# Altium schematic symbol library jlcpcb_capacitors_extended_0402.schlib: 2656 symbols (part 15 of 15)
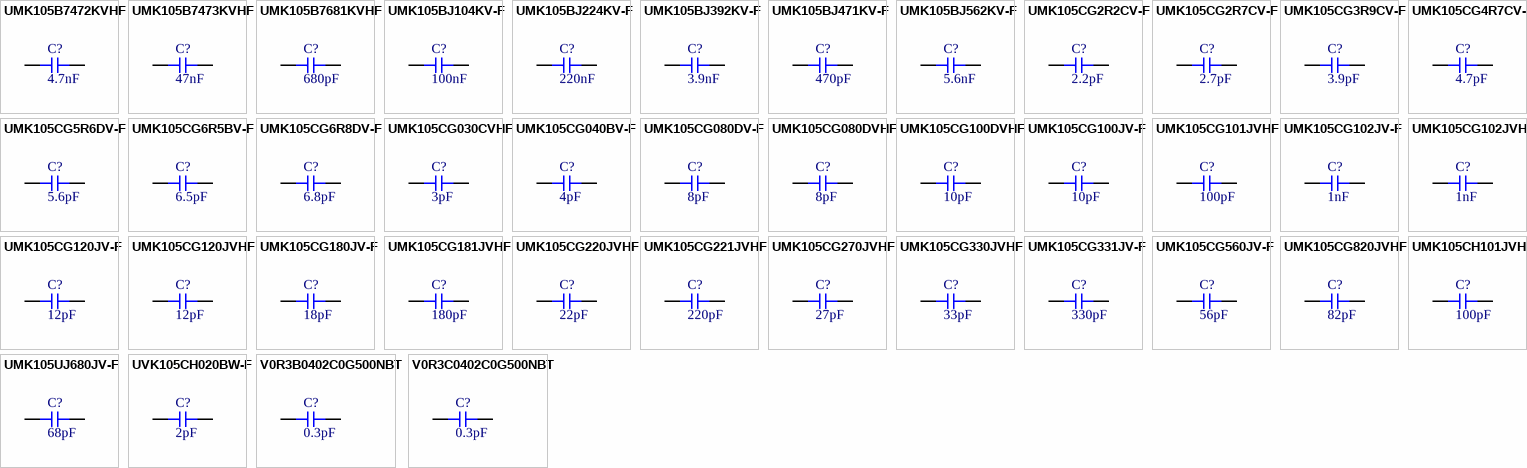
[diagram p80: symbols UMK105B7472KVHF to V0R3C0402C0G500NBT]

## UMK105CH101JVHF
designator C?  Capacitance: 100pF  (hidden comment: *)
Capacitor, Ceramic (MLCC), 100pF, ±5%, 50V, ±5%, SMD 0402; Manufacturer: Taiyo Yuden; Manufacturer Part Number: UMK105CH101JVHF
footprint CAP-0402 (0402 (1005M) Capacitor)
pins: 1, 2

## UMK105UJ680JV-F
designator C?  Capacitance: 68pF  (hidden comment: *)
Capacitor, Ceramic (MLCC), 68pF, ±5%, 50V, U2J, ±5%, SMD 0402; Manufacturer: Taiyo Yuden; Manufacturer Part Number: UMK105UJ680JV-F
footprint CAP-0402 (0402 (1005M) Capacitor)
pins: 1, 2

## UVK105CH020BW-F
designator C?  Capacitance: 2pF  (hidden comment: *)
Capacitor, Ceramic (MLCC), 2pF, ±0.1pF, 50V, ±0.1pF, SMD 0402; Manufacturer: Taiyo Yuden; Manufacturer Part Number: UVK105CH020BW-F
footprint CAP-0402 (0402 (1005M) Capacitor)
pins: 1, 2

## V0R3B0402C0G500NBT
designator C?  Capacitance: 0.3pF  (hidden comment: *)
Capacitor, Ceramic (MLCC), 0.3pF, ±0.1pF, 50V, C0G, ±0.1pF, SMD 0402; Manufacturer: VIIYONG; Manufacturer Part Number: V0R3B0402C0G500NBT
footprint CAP-0402 (0402 (1005M) Capacitor)
pins: 1, 2

## V0R3C0402C0G500NBT
designator C?  Capacitance: 0.3pF  (hidden comment: *)
Capacitor, Ceramic (MLCC), 0.3pF, ±0.25pF, 50V, C0G, ±0.25pF, SMD 0402; Manufacturer: VIIYONG; Manufacturer Part Number: V0R3C0402C0G500NBT
footprint CAP-0402 (0402 (1005M) Capacitor)
pins: 1, 2

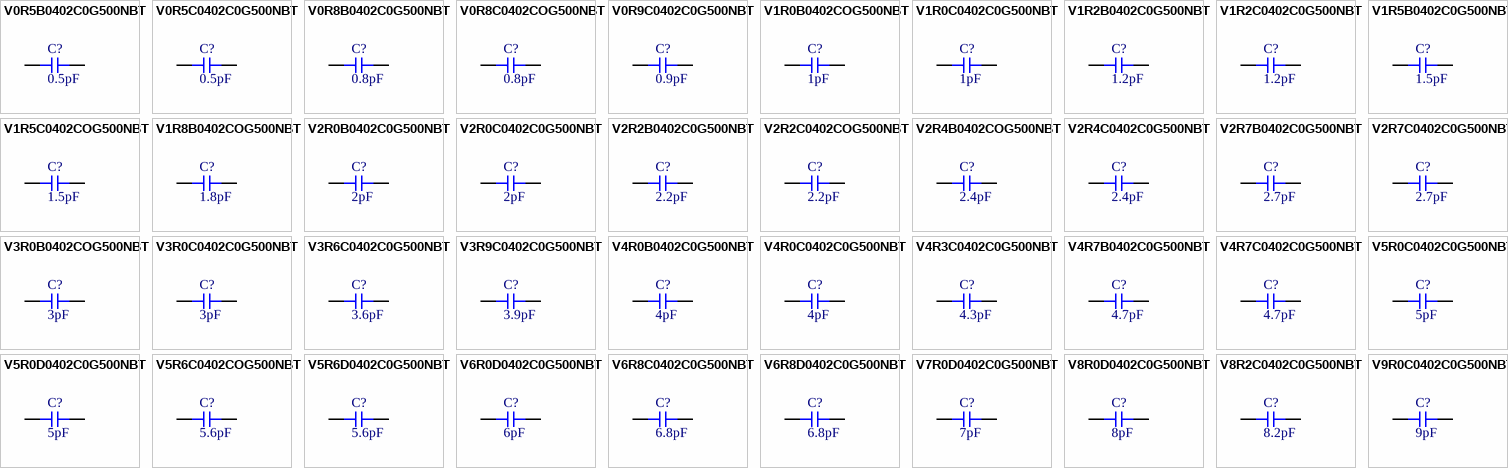
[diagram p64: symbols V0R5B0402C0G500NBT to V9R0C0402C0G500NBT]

## V0R5B0402C0G500NBT
designator C?  Capacitance: 0.5pF  (hidden comment: *)
Capacitor, Ceramic (MLCC), 0.5pF, ±0.1pF, 50V, C0G, ±0.1pF, SMD 0402; Manufacturer: VIIYONG; Manufacturer Part Number: V0R5B0402C0G500NBT
footprint CAP-0402 (0402 (1005M) Capacitor)
pins: 1, 2

## V0R5C0402C0G500NBT
designator C?  Capacitance: 0.5pF  (hidden comment: *)
Capacitor, Ceramic (MLCC), 0.5pF, ±0.25pF, 50V, C0G, ±0.25pF, SMD 0402; Manufacturer: VIIYONG; Manufacturer Part Number: V0R5C0402C0G500NBT
footprint CAP-0402 (0402 (1005M) Capacitor)
pins: 1, 2

## V0R8B0402C0G500NBT
designator C?  Capacitance: 0.8pF  (hidden comment: *)
Capacitor, Ceramic (MLCC), 0.8pF, ±0.1pF, 50V, C0G, ±0.1pF, SMD 0402; Manufacturer: VIIYONG; Manufacturer Part Number: V0R8B0402C0G500NBT
footprint CAP-0402 (0402 (1005M) Capacitor)
pins: 1, 2

## V0R8C0402COG500NBT
designator C?  Capacitance: 0.8pF  (hidden comment: *)
Capacitor, Ceramic (MLCC), 0.8pF, ±0.25pF, 50V, C0G, ±0.25pF, SMD 0402; Manufacturer: VIIYONG; Manufacturer Part Number: V0R8C0402COG500NBT
footprint CAP-0402 (0402 (1005M) Capacitor)
pins: 1, 2

## V0R9C0402C0G500NBT
designator C?  Capacitance: 0.9pF  (hidden comment: *)
Capacitor, Ceramic (MLCC), 0.9pF, ±0.25pF, 50V, C0G, ±0.25pF, SMD 0402; Manufacturer: VIIYONG; Manufacturer Part Number: V0R9C0402C0G500NBT
footprint CAP-0402 (0402 (1005M) Capacitor)
pins: 1, 2

## V1R0B0402COG500NBT
designator C?  Capacitance: 1pF  (hidden comment: *)
Capacitor, Ceramic (MLCC), 1pF, ±0.1pF, 50V, C0G, ±0.1pF, SMD 0402; Manufacturer: VIIYONG; Manufacturer Part Number: V1R0B0402COG500NBT
footprint CAP-0402 (0402 (1005M) Capacitor)
pins: 1, 2

## V1R0C0402C0G500NBT
designator C?  Capacitance: 1pF  (hidden comment: *)
Capacitor, Ceramic (MLCC), 1pF, ±0.25pF, 50V, C0G, ±0.25pF, SMD 0402; Manufacturer: VIIYONG; Manufacturer Part Number: V1R0C0402C0G500NBT
footprint CAP-0402 (0402 (1005M) Capacitor)
pins: 1, 2

## V1R2B0402C0G500NBT
designator C?  Capacitance: 1.2pF  (hidden comment: *)
Capacitor, Ceramic (MLCC), 1.2pF, ±0.1pF, 50V, C0G, ±0.1pF, SMD 0402; Manufacturer: VIIYONG; Manufacturer Part Number: V1R2B0402C0G500NBT
footprint CAP-0402 (0402 (1005M) Capacitor)
pins: 1, 2

## V1R2C0402C0G500NBT
designator C?  Capacitance: 1.2pF  (hidden comment: *)
Capacitor, Ceramic (MLCC), 1.2pF, ±0.25pF, 50V, C0G, ±0.25pF, SMD 0402; Manufacturer: VIIYONG; Manufacturer Part Number: V1R2C0402C0G500NBT
footprint CAP-0402 (0402 (1005M) Capacitor)
pins: 1, 2

## V1R5B0402C0G500NBT
designator C?  Capacitance: 1.5pF  (hidden comment: *)
Capacitor, Ceramic (MLCC), 1.5pF, ±0.1pF, 50V, C0G, ±0.1pF, SMD 0402; Manufacturer: VIIYONG; Manufacturer Part Number: V1R5B0402C0G500NBT
footprint CAP-0402 (0402 (1005M) Capacitor)
pins: 1, 2

## V1R5C0402COG500NBT
designator C?  Capacitance: 1.5pF  (hidden comment: *)
Capacitor, Ceramic (MLCC), 1.5pF, ±0.25pF, 50V, C0G, ±0.25pF, SMD 0402; Manufacturer: VIIYONG; Manufacturer Part Number: V1R5C0402COG500NBT
footprint CAP-0402 (0402 (1005M) Capacitor)
pins: 1, 2

## V1R8B0402COG500NBT
designator C?  Capacitance: 1.8pF  (hidden comment: *)
Capacitor, Ceramic (MLCC), 1.8pF, ±0.1pF, 50V, C0G, ±0.1pF, SMD 0402; Manufacturer: VIIYONG; Manufacturer Part Number: V1R8B0402COG500NBT
footprint CAP-0402 (0402 (1005M) Capacitor)
pins: 1, 2

## V2R0B0402C0G500NBT
designator C?  Capacitance: 2pF  (hidden comment: *)
Capacitor, Ceramic (MLCC), 2pF, ±0.1pF, 50V, C0G, ±0.1pF, SMD 0402; Manufacturer: VIIYONG; Manufacturer Part Number: V2R0B0402C0G500NBT
footprint CAP-0402 (0402 (1005M) Capacitor)
pins: 1, 2

## V2R0C0402C0G500NBT
designator C?  Capacitance: 2pF  (hidden comment: *)
Capacitor, Ceramic (MLCC), 2pF, ±0.25pF, 50V, C0G, ±0.25pF, SMD 0402; Manufacturer: VIIYONG; Manufacturer Part Number: V2R0C0402C0G500NBT
footprint CAP-0402 (0402 (1005M) Capacitor)
pins: 1, 2

## V2R2B0402C0G500NBT
designator C?  Capacitance: 2.2pF  (hidden comment: *)
Capacitor, Ceramic (MLCC), 2.2pF, ±0.1pF, 50V, C0G, ±0.1pF, SMD 0402; Manufacturer: VIIYONG; Manufacturer Part Number: V2R2B0402C0G500NBT
footprint CAP-0402 (0402 (1005M) Capacitor)
pins: 1, 2

## V2R2C0402COG500NBT
designator C?  Capacitance: 2.2pF  (hidden comment: *)
Capacitor, Ceramic (MLCC), 2.2pF, ±0.25pF, 50V, C0G, ±0.25pF, SMD 0402; Manufacturer: VIIYONG; Manufacturer Part Number: V2R2C0402COG500NBT
footprint CAP-0402 (0402 (1005M) Capacitor)
pins: 1, 2

## V2R4B0402COG500NBT
designator C?  Capacitance: 2.4pF  (hidden comment: *)
Capacitor, Ceramic (MLCC), 2.4pF, ±0.1pF, 50V, C0G, ±0.1pF, SMD 0402; Manufacturer: VIIYONG; Manufacturer Part Number: V2R4B0402COG500NBT
footprint CAP-0402 (0402 (1005M) Capacitor)
pins: 1, 2

## V2R4C0402C0G500NBT
designator C?  Capacitance: 2.4pF  (hidden comment: *)
Capacitor, Ceramic (MLCC), 2.4pF, ±0.25pF, 50V, C0G, ±0.25pF, SMD 0402; Manufacturer: VIIYONG; Manufacturer Part Number: V2R4C0402C0G500NBT
footprint CAP-0402 (0402 (1005M) Capacitor)
pins: 1, 2

## V2R7B0402C0G500NBT
designator C?  Capacitance: 2.7pF  (hidden comment: *)
Capacitor, Ceramic (MLCC), 2.7pF, ±0.1pF, 50V, C0G, ±0.1pF, SMD 0402; Manufacturer: VIIYONG; Manufacturer Part Number: V2R7B0402C0G500NBT
footprint CAP-0402 (0402 (1005M) Capacitor)
pins: 1, 2

## V2R7C0402C0G500NBT
designator C?  Capacitance: 2.7pF  (hidden comment: *)
Capacitor, Ceramic (MLCC), 2.7pF, ±0.25pF, 50V, C0G, ±0.25pF, SMD 0402; Manufacturer: VIIYONG; Manufacturer Part Number: V2R7C0402C0G500NBT
footprint CAP-0402 (0402 (1005M) Capacitor)
pins: 1, 2

## V3R0B0402COG500NBT
designator C?  Capacitance: 3pF  (hidden comment: *)
Capacitor, Ceramic (MLCC), 3pF, ±0.1pF, 50V, C0G, ±0.1pF, SMD 0402; Manufacturer: VIIYONG; Manufacturer Part Number: V3R0B0402COG500NBT
footprint CAP-0402 (0402 (1005M) Capacitor)
pins: 1, 2

## V3R0C0402C0G500NBT
designator C?  Capacitance: 3pF  (hidden comment: *)
Capacitor, Ceramic (MLCC), 3pF, ±0.25pF, 50V, C0G, ±0.25pF, SMD 0402; Manufacturer: VIIYONG; Manufacturer Part Number: V3R0C0402C0G500NBT
footprint CAP-0402 (0402 (1005M) Capacitor)
pins: 1, 2

## V3R6C0402C0G500NBT
designator C?  Capacitance: 3.6pF  (hidden comment: *)
Capacitor, Ceramic (MLCC), 3.6pF, ±0.25pF, 50V, C0G, ±0.25pF, SMD 0402; Manufacturer: VIIYONG; Manufacturer Part Number: V3R6C0402C0G500NBT
footprint CAP-0402 (0402 (1005M) Capacitor)
pins: 1, 2

## V3R9C0402C0G500NBT
designator C?  Capacitance: 3.9pF  (hidden comment: *)
Capacitor, Ceramic (MLCC), 3.9pF, ±0.25pF, 50V, C0G, ±0.25pF, SMD 0402; Manufacturer: VIIYONG; Manufacturer Part Number: V3R9C0402C0G500NBT
footprint CAP-0402 (0402 (1005M) Capacitor)
pins: 1, 2

## V4R0B0402C0G500NBT
designator C?  Capacitance: 4pF  (hidden comment: *)
Capacitor, Ceramic (MLCC), 4pF, ±0.1pF, 50V, C0G, ±0.1pF, SMD 0402; Manufacturer: VIIYONG; Manufacturer Part Number: V4R0B0402C0G500NBT
footprint CAP-0402 (0402 (1005M) Capacitor)
pins: 1, 2

## V4R0C0402C0G500NBT
designator C?  Capacitance: 4pF  (hidden comment: *)
Capacitor, Ceramic (MLCC), 4pF, ±0.25pF, 50V, C0G, ±0.25pF, SMD 0402; Manufacturer: VIIYONG; Manufacturer Part Number: V4R0C0402C0G500NBT
footprint CAP-0402 (0402 (1005M) Capacitor)
pins: 1, 2

## V4R3C0402C0G500NBT
designator C?  Capacitance: 4.3pF  (hidden comment: *)
Capacitor, Ceramic (MLCC), 4.3pF, ±0.25pF, 50V, C0G, ±0.25pF, SMD 0402; Manufacturer: VIIYONG; Manufacturer Part Number: V4R3C0402C0G500NBT
footprint CAP-0402 (0402 (1005M) Capacitor)
pins: 1, 2

## V4R7B0402C0G500NBT
designator C?  Capacitance: 4.7pF  (hidden comment: *)
Capacitor, Ceramic (MLCC), 4.7pF, ±0.1pF, 50V, C0G, ±0.1pF, SMD 0402; Manufacturer: VIIYONG; Manufacturer Part Number: V4R7B0402C0G500NBT
footprint CAP-0402 (0402 (1005M) Capacitor)
pins: 1, 2

## V4R7C0402C0G500NBT
designator C?  Capacitance: 4.7pF  (hidden comment: *)
Capacitor, Ceramic (MLCC), 4.7pF, ±0.25pF, 50V, C0G, ±0.25pF, SMD 0402; Manufacturer: VIIYONG; Manufacturer Part Number: V4R7C0402C0G500NBT
footprint CAP-0402 (0402 (1005M) Capacitor)
pins: 1, 2

## V5R0C0402C0G500NBT
designator C?  Capacitance: 5pF  (hidden comment: *)
Capacitor, Ceramic (MLCC), 5pF, ±0.25pF, 50V, C0G, ±0.25pF, SMD 0402; Manufacturer: VIIYONG; Manufacturer Part Number: V5R0C0402C0G500NBT
footprint CAP-0402 (0402 (1005M) Capacitor)
pins: 1, 2

## V5R0D0402C0G500NBT
designator C?  Capacitance: 5pF  (hidden comment: *)
Capacitor, Ceramic (MLCC), 5pF, ±0.5pF, 50V, C0G, ±0.5pF, SMD 0402; Manufacturer: VIIYONG; Manufacturer Part Number: V5R0D0402C0G500NBT
footprint CAP-0402 (0402 (1005M) Capacitor)
pins: 1, 2

## V5R6C0402COG500NBT
designator C?  Capacitance: 5.6pF  (hidden comment: *)
Capacitor, Ceramic (MLCC), 5.6pF, ±0.25pF, 50V, C0G, ±0.25pF, SMD 0402; Manufacturer: VIIYONG; Manufacturer Part Number: V5R6C0402COG500NBT
footprint CAP-0402 (0402 (1005M) Capacitor)
pins: 1, 2

## V5R6D0402C0G500NBT
designator C?  Capacitance: 5.6pF  (hidden comment: *)
Capacitor, Ceramic (MLCC), 5.6pF, ±0.5pF, 50V, C0G, ±0.5pF, SMD 0402; Manufacturer: VIIYONG; Manufacturer Part Number: V5R6D0402C0G500NBT
footprint CAP-0402 (0402 (1005M) Capacitor)
pins: 1, 2

## V6R0D0402C0G500NBT
designator C?  Capacitance: 6pF  (hidden comment: *)
Capacitor, Ceramic (MLCC), 6pF, ±0.5pF, 50V, C0G, ±0.5pF, SMD 0402; Manufacturer: VIIYONG; Manufacturer Part Number: V6R0D0402C0G500NBT
footprint CAP-0402 (0402 (1005M) Capacitor)
pins: 1, 2

## V6R8C0402C0G500NBT
designator C?  Capacitance: 6.8pF  (hidden comment: *)
Capacitor, Ceramic (MLCC), 6.8pF, ±0.25pF, 50V, C0G, ±0.25pF, SMD 0402; Manufacturer: VIIYONG; Manufacturer Part Number: V6R8C0402C0G500NBT
footprint CAP-0402 (0402 (1005M) Capacitor)
pins: 1, 2

## V6R8D0402C0G500NBT
designator C?  Capacitance: 6.8pF  (hidden comment: *)
Capacitor, Ceramic (MLCC), 6.8pF, ±0.5pF, 50V, C0G, ±0.5pF, SMD 0402; Manufacturer: VIIYONG; Manufacturer Part Number: V6R8D0402C0G500NBT
footprint CAP-0402 (0402 (1005M) Capacitor)
pins: 1, 2

## V7R0D0402C0G500NBT
designator C?  Capacitance: 7pF  (hidden comment: *)
Capacitor, Ceramic (MLCC), 7pF, ±0.5pF, 50V, C0G, ±0.5pF, SMD 0402; Manufacturer: VIIYONG; Manufacturer Part Number: V7R0D0402C0G500NBT
footprint CAP-0402 (0402 (1005M) Capacitor)
pins: 1, 2

## V8R0D0402C0G500NBT
designator C?  Capacitance: 8pF  (hidden comment: *)
Capacitor, Ceramic (MLCC), 8pF, ±0.5pF, 50V, C0G, ±0.5pF, SMD 0402; Manufacturer: VIIYONG; Manufacturer Part Number: V8R0D0402C0G500NBT
footprint CAP-0402 (0402 (1005M) Capacitor)
pins: 1, 2

## V8R2C0402C0G500NBT
designator C?  Capacitance: 8.2pF  (hidden comment: *)
Capacitor, Ceramic (MLCC), 8.2pF, ±0.25pF, 50V, C0G, ±0.25pF, SMD 0402; Manufacturer: VIIYONG; Manufacturer Part Number: V8R2C0402C0G500NBT
footprint CAP-0402 (0402 (1005M) Capacitor)
pins: 1, 2

## V9R0C0402C0G500NBT
designator C?  Capacitance: 9pF  (hidden comment: *)
Capacitor, Ceramic (MLCC), 9pF, ±0.25pF, 50V, C0G, ±0.25pF, SMD 0402; Manufacturer: VIIYONG; Manufacturer Part Number: V9R0C0402C0G500NBT
footprint CAP-0402 (0402 (1005M) Capacitor)
pins: 1, 2

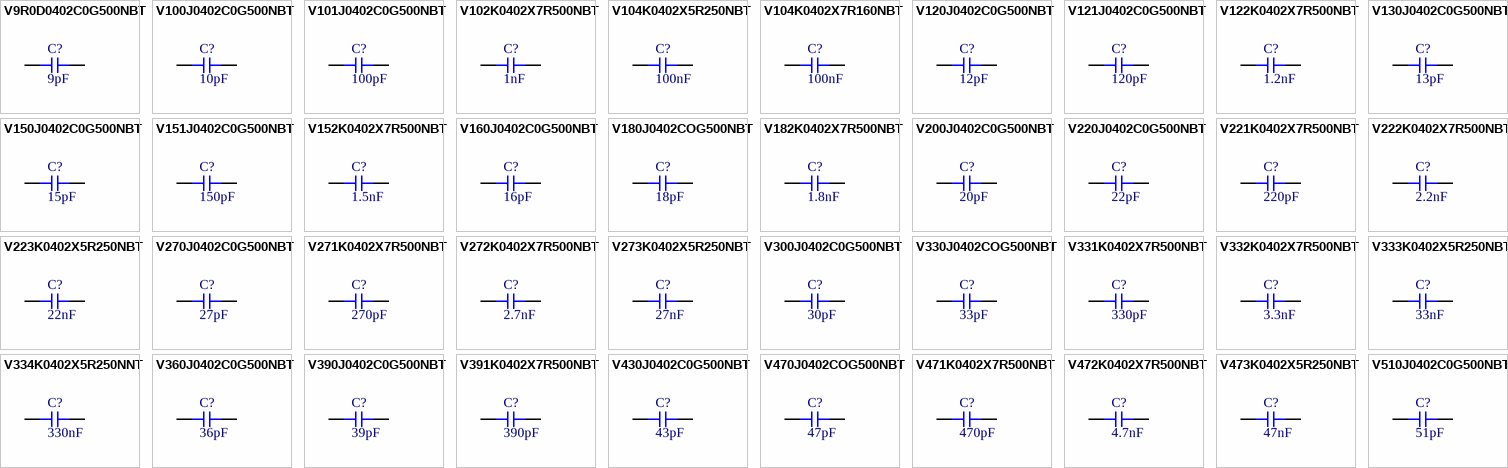
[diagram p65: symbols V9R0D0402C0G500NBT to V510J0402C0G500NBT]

## V9R0D0402C0G500NBT
designator C?  Capacitance: 9pF  (hidden comment: *)
Capacitor, Ceramic (MLCC), 9pF, ±0.5pF, 50V, C0G, ±0.5pF, SMD 0402; Manufacturer: VIIYONG; Manufacturer Part Number: V9R0D0402C0G500NBT
footprint CAP-0402 (0402 (1005M) Capacitor)
pins: 1, 2

## V100J0402C0G500NBT
designator C?  Capacitance: 10pF  (hidden comment: *)
Capacitor, Ceramic (MLCC), 10pF, ±5%, 50V, C0G, ±5%, SMD 0402; Manufacturer: VIIYONG; Manufacturer Part Number: V100J0402C0G500NBT
footprint CAP-0402 (0402 (1005M) Capacitor)
pins: 1, 2

## V101J0402C0G500NBT
designator C?  Capacitance: 100pF  (hidden comment: *)
Capacitor, Ceramic (MLCC), 100pF, ±5%, 50V, C0G, ±5%, SMD 0402; Manufacturer: VIIYONG; Manufacturer Part Number: V101J0402C0G500NBT
footprint CAP-0402 (0402 (1005M) Capacitor)
pins: 1, 2

## V102K0402X7R500NBT
designator C?  Capacitance: 1nF  (hidden comment: *)
Capacitor, Ceramic (MLCC), 1nF, ±10%, 50V, X7R, ±10%, SMD 0402; Manufacturer: VIIYONG; Manufacturer Part Number: V102K0402X7R500NBT
footprint CAP-0402 (0402 (1005M) Capacitor)
pins: 1, 2

## V104K0402X5R250NBT
designator C?  Capacitance: 100nF  (hidden comment: *)
Capacitor, Ceramic (MLCC), 100nF, ±10%, 25V, X5R, ±10%, SMD 0402; Manufacturer: VIIYONG; Manufacturer Part Number: V104K0402X5R250NBT
footprint CAP-0402 (0402 (1005M) Capacitor)
pins: 1, 2

## V104K0402X7R160NBT
designator C?  Capacitance: 100nF  (hidden comment: *)
Capacitor, Ceramic (MLCC), 100nF, ±10%, 16V, X7R, ±10%, SMD 0402; Manufacturer: VIIYONG; Manufacturer Part Number: V104K0402X7R160NBT
footprint CAP-0402 (0402 (1005M) Capacitor)
pins: 1, 2

## V120J0402C0G500NBT
designator C?  Capacitance: 12pF  (hidden comment: *)
Capacitor, Ceramic (MLCC), 12pF, ±5%, 50V, C0G, ±5%, SMD 0402; Manufacturer: VIIYONG; Manufacturer Part Number: V120J0402C0G500NBT
footprint CAP-0402 (0402 (1005M) Capacitor)
pins: 1, 2

## V121J0402C0G500NBT
designator C?  Capacitance: 120pF  (hidden comment: *)
Capacitor, Ceramic (MLCC), 120pF, ±5%, 50V, C0G, ±5%, SMD 0402; Manufacturer: VIIYONG; Manufacturer Part Number: V121J0402C0G500NBT
footprint CAP-0402 (0402 (1005M) Capacitor)
pins: 1, 2

## V122K0402X7R500NBT
designator C?  Capacitance: 1.2nF  (hidden comment: *)
Capacitor, Ceramic (MLCC), 1.2nF, ±10%, 50V, X7R, ±10%, SMD 0402; Manufacturer: VIIYONG; Manufacturer Part Number: V122K0402X7R500NBT
footprint CAP-0402 (0402 (1005M) Capacitor)
pins: 1, 2

## V130J0402C0G500NBT
designator C?  Capacitance: 13pF  (hidden comment: *)
Capacitor, Ceramic (MLCC), 13pF, ±5%, 50V, C0G, ±5%, SMD 0402; Manufacturer: VIIYONG; Manufacturer Part Number: V130J0402C0G500NBT
footprint CAP-0402 (0402 (1005M) Capacitor)
pins: 1, 2

## V150J0402C0G500NBT
designator C?  Capacitance: 15pF  (hidden comment: *)
Capacitor, Ceramic (MLCC), 15pF, ±5%, 50V, C0G, ±5%, SMD 0402; Manufacturer: VIIYONG; Manufacturer Part Number: V150J0402C0G500NBT
footprint CAP-0402 (0402 (1005M) Capacitor)
pins: 1, 2

## V151J0402C0G500NBT
designator C?  Capacitance: 150pF  (hidden comment: *)
Capacitor, Ceramic (MLCC), 150pF, ±5%, 50V, C0G, ±5%, SMD 0402; Manufacturer: VIIYONG; Manufacturer Part Number: V151J0402C0G500NBT
footprint CAP-0402 (0402 (1005M) Capacitor)
pins: 1, 2

## V152K0402X7R500NBT
designator C?  Capacitance: 1.5nF  (hidden comment: *)
Capacitor, Ceramic (MLCC), 1.5nF, ±10%, 50V, X7R, ±10%, SMD 0402; Manufacturer: VIIYONG; Manufacturer Part Number: V152K0402X7R500NBT
footprint CAP-0402 (0402 (1005M) Capacitor)
pins: 1, 2

## V160J0402C0G500NBT
designator C?  Capacitance: 16pF  (hidden comment: *)
Capacitor, Ceramic (MLCC), 16pF, ±5%, 50V, C0G, ±5%, SMD 0402; Manufacturer: VIIYONG; Manufacturer Part Number: V160J0402C0G500NBT
footprint CAP-0402 (0402 (1005M) Capacitor)
pins: 1, 2

## V180J0402COG500NBT
designator C?  Capacitance: 18pF  (hidden comment: *)
Capacitor, Ceramic (MLCC), 18pF, ±5%, 50V, C0G, ±5%, SMD 0402; Manufacturer: VIIYONG; Manufacturer Part Number: V180J0402COG500NBT
footprint CAP-0402 (0402 (1005M) Capacitor)
pins: 1, 2

## V182K0402X7R500NBT
designator C?  Capacitance: 1.8nF  (hidden comment: *)
Capacitor, Ceramic (MLCC), 1.8nF, ±10%, 50V, X7R, ±10%, SMD 0402; Manufacturer: VIIYONG; Manufacturer Part Number: V182K0402X7R500NBT
footprint CAP-0402 (0402 (1005M) Capacitor)
pins: 1, 2

## V200J0402C0G500NBT
designator C?  Capacitance: 20pF  (hidden comment: *)
Capacitor, Ceramic (MLCC), 20pF, ±5%, 50V, C0G, ±5%, SMD 0402; Manufacturer: VIIYONG; Manufacturer Part Number: V200J0402C0G500NBT
footprint CAP-0402 (0402 (1005M) Capacitor)
pins: 1, 2

## V220J0402C0G500NBT
designator C?  Capacitance: 22pF  (hidden comment: *)
Capacitor, Ceramic (MLCC), 22pF, ±5%, 50V, C0G, ±5%, SMD 0402; Manufacturer: VIIYONG; Manufacturer Part Number: V220J0402C0G500NBT
footprint CAP-0402 (0402 (1005M) Capacitor)
pins: 1, 2

## V221K0402X7R500NBT
designator C?  Capacitance: 220pF  (hidden comment: *)
Capacitor, Ceramic (MLCC), 220pF, ±10%, 50V, X7R, ±10%, SMD 0402; Manufacturer: VIIYONG; Manufacturer Part Number: V221K0402X7R500NBT
footprint CAP-0402 (0402 (1005M) Capacitor)
pins: 1, 2

## V222K0402X7R500NBT
designator C?  Capacitance: 2.2nF  (hidden comment: *)
Capacitor, Ceramic (MLCC), 2.2nF, ±10%, 50V, X7R, ±10%, SMD 0402; Manufacturer: VIIYONG; Manufacturer Part Number: V222K0402X7R500NBT
footprint CAP-0402 (0402 (1005M) Capacitor)
pins: 1, 2

## V223K0402X5R250NBT
designator C?  Capacitance: 22nF  (hidden comment: *)
Capacitor, Ceramic (MLCC), 22nF, ±10%, 25V, X5R, ±10%, SMD 0402; Manufacturer: VIIYONG; Manufacturer Part Number: V223K0402X5R250NBT
footprint CAP-0402 (0402 (1005M) Capacitor)
pins: 1, 2

## V270J0402C0G500NBT
designator C?  Capacitance: 27pF  (hidden comment: *)
Capacitor, Ceramic (MLCC), 27pF, ±5%, 50V, C0G, ±5%, SMD 0402; Manufacturer: VIIYONG; Manufacturer Part Number: V270J0402C0G500NBT
footprint CAP-0402 (0402 (1005M) Capacitor)
pins: 1, 2

## V271K0402X7R500NBT
designator C?  Capacitance: 270pF  (hidden comment: *)
Capacitor, Ceramic (MLCC), 270pF, ±10%, 50V, X7R, ±10%, SMD 0402; Manufacturer: VIIYONG; Manufacturer Part Number: V271K0402X7R500NBT
footprint CAP-0402 (0402 (1005M) Capacitor)
pins: 1, 2

## V272K0402X7R500NBT
designator C?  Capacitance: 2.7nF  (hidden comment: *)
Capacitor, Ceramic (MLCC), 2.7nF, ±10%, 50V, X7R, ±10%, SMD 0402; Manufacturer: VIIYONG; Manufacturer Part Number: V272K0402X7R500NBT
footprint CAP-0402 (0402 (1005M) Capacitor)
pins: 1, 2

## V273K0402X5R250NBT
designator C?  Capacitance: 27nF  (hidden comment: *)
Capacitor, Ceramic (MLCC), 27nF, ±10%, 25V, X5R, ±10%, SMD 0402; Manufacturer: VIIYONG; Manufacturer Part Number: V273K0402X5R250NBT
footprint CAP-0402 (0402 (1005M) Capacitor)
pins: 1, 2

## V300J0402C0G500NBT
designator C?  Capacitance: 30pF  (hidden comment: *)
Capacitor, Ceramic (MLCC), 30pF, ±5%, 50V, C0G, ±5%, SMD 0402; Manufacturer: VIIYONG; Manufacturer Part Number: V300J0402C0G500NBT
footprint CAP-0402 (0402 (1005M) Capacitor)
pins: 1, 2

## V330J0402COG500NBT
designator C?  Capacitance: 33pF  (hidden comment: *)
Capacitor, Ceramic (MLCC), 33pF, ±5%, 50V, C0G, ±5%, SMD 0402; Manufacturer: VIIYONG; Manufacturer Part Number: V330J0402COG500NBT
footprint CAP-0402 (0402 (1005M) Capacitor)
pins: 1, 2

## V331K0402X7R500NBT
designator C?  Capacitance: 330pF  (hidden comment: *)
Capacitor, Ceramic (MLCC), 330pF, ±10%, 50V, X7R, ±10%, SMD 0402; Manufacturer: VIIYONG; Manufacturer Part Number: V331K0402X7R500NBT
footprint CAP-0402 (0402 (1005M) Capacitor)
pins: 1, 2

## V332K0402X7R500NBT
designator C?  Capacitance: 3.3nF  (hidden comment: *)
Capacitor, Ceramic (MLCC), 3.3nF, ±10%, 50V, X7R, ±10%, SMD 0402; Manufacturer: VIIYONG; Manufacturer Part Number: V332K0402X7R500NBT
footprint CAP-0402 (0402 (1005M) Capacitor)
pins: 1, 2

## V333K0402X5R250NBT
designator C?  Capacitance: 33nF  (hidden comment: *)
Capacitor, Ceramic (MLCC), 33nF, ±10%, 25V, X5R, ±10%, SMD 0402; Manufacturer: VIIYONG; Manufacturer Part Number: V333K0402X5R250NBT
footprint CAP-0402 (0402 (1005M) Capacitor)
pins: 1, 2

## V334K0402X5R250NNT
designator C?  Capacitance: 330nF  (hidden comment: *)
Capacitor, Ceramic (MLCC), 330nF, ±10%, 25V, X5R, ±10%, SMD 0402; Manufacturer: VIIYONG; Manufacturer Part Number: V334K0402X5R250NNT
footprint CAP-0402 (0402 (1005M) Capacitor)
pins: 1, 2

## V360J0402C0G500NBT
designator C?  Capacitance: 36pF  (hidden comment: *)
Capacitor, Ceramic (MLCC), 36pF, ±5%, 50V, C0G, ±5%, SMD 0402; Manufacturer: VIIYONG; Manufacturer Part Number: V360J0402C0G500NBT
footprint CAP-0402 (0402 (1005M) Capacitor)
pins: 1, 2

## V390J0402C0G500NBT
designator C?  Capacitance: 39pF  (hidden comment: *)
Capacitor, Ceramic (MLCC), 39pF, ±5%, 50V, C0G, ±5%, SMD 0402; Manufacturer: VIIYONG; Manufacturer Part Number: V390J0402C0G500NBT
footprint CAP-0402 (0402 (1005M) Capacitor)
pins: 1, 2

## V391K0402X7R500NBT
designator C?  Capacitance: 390pF  (hidden comment: *)
Capacitor, Ceramic (MLCC), 390pF, ±10%, 50V, X7R, ±10%, SMD 0402; Manufacturer: VIIYONG; Manufacturer Part Number: V391K0402X7R500NBT
footprint CAP-0402 (0402 (1005M) Capacitor)
pins: 1, 2

## V430J0402C0G500NBT
designator C?  Capacitance: 43pF  (hidden comment: *)
Capacitor, Ceramic (MLCC), 43pF, ±5%, 50V, C0G, ±5%, SMD 0402; Manufacturer: VIIYONG; Manufacturer Part Number: V430J0402C0G500NBT
footprint CAP-0402 (0402 (1005M) Capacitor)
pins: 1, 2

## V470J0402COG500NBT
designator C?  Capacitance: 47pF  (hidden comment: *)
Capacitor, Ceramic (MLCC), 47pF, ±5%, 50V, C0G, ±5%, SMD 0402; Manufacturer: VIIYONG; Manufacturer Part Number: V470J0402COG500NBT
footprint CAP-0402 (0402 (1005M) Capacitor)
pins: 1, 2

## V471K0402X7R500NBT
designator C?  Capacitance: 470pF  (hidden comment: *)
Capacitor, Ceramic (MLCC), 470pF, ±10%, 50V, X7R, ±10%, SMD 0402; Manufacturer: VIIYONG; Manufacturer Part Number: V471K0402X7R500NBT
footprint CAP-0402 (0402 (1005M) Capacitor)
pins: 1, 2

## V472K0402X7R500NBT
designator C?  Capacitance: 4.7nF  (hidden comment: *)
Capacitor, Ceramic (MLCC), 4.7nF, ±10%, 50V, X7R, ±10%, SMD 0402; Manufacturer: VIIYONG; Manufacturer Part Number: V472K0402X7R500NBT
footprint CAP-0402 (0402 (1005M) Capacitor)
pins: 1, 2

## V473K0402X5R250NBT
designator C?  Capacitance: 47nF  (hidden comment: *)
Capacitor, Ceramic (MLCC), 47nF, ±10%, 25V, X5R, ±10%, SMD 0402; Manufacturer: VIIYONG; Manufacturer Part Number: V473K0402X5R250NBT
footprint CAP-0402 (0402 (1005M) Capacitor)
pins: 1, 2

## V510J0402C0G500NBT
designator C?  Capacitance: 51pF  (hidden comment: *)
Capacitor, Ceramic (MLCC), 51pF, ±5%, 50V, C0G, ±5%, SMD 0402; Manufacturer: VIIYONG; Manufacturer Part Number: V510J0402C0G500NBT
footprint CAP-0402 (0402 (1005M) Capacitor)
pins: 1, 2

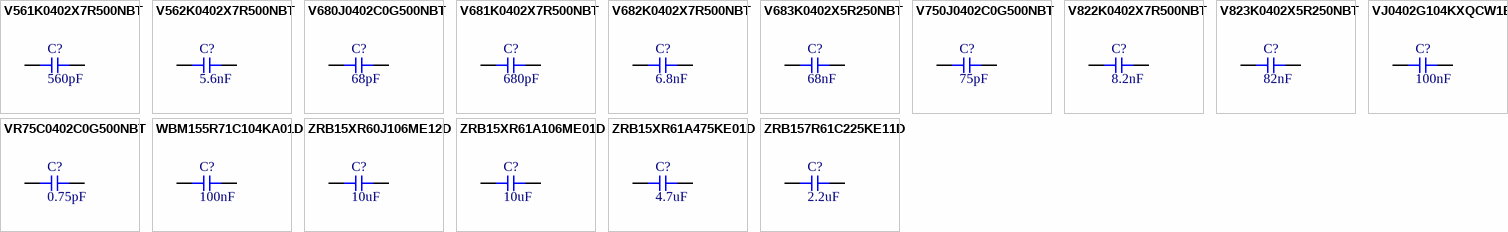
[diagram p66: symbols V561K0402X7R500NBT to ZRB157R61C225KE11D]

## V561K0402X7R500NBT
designator C?  Capacitance: 560pF  (hidden comment: *)
Capacitor, Ceramic (MLCC), 560pF, ±10%, 50V, X7R, ±10%, SMD 0402; Manufacturer: VIIYONG; Manufacturer Part Number: V561K0402X7R500NBT
footprint CAP-0402 (0402 (1005M) Capacitor)
pins: 1, 2

## V562K0402X7R500NBT
designator C?  Capacitance: 5.6nF  (hidden comment: *)
Capacitor, Ceramic (MLCC), 5.6nF, ±10%, 50V, X7R, ±10%, SMD 0402; Manufacturer: VIIYONG; Manufacturer Part Number: V562K0402X7R500NBT
footprint CAP-0402 (0402 (1005M) Capacitor)
pins: 1, 2

## V680J0402C0G500NBT
designator C?  Capacitance: 68pF  (hidden comment: *)
Capacitor, Ceramic (MLCC), 68pF, ±5%, 50V, C0G, ±5%, SMD 0402; Manufacturer: VIIYONG; Manufacturer Part Number: V680J0402C0G500NBT
footprint CAP-0402 (0402 (1005M) Capacitor)
pins: 1, 2

## V681K0402X7R500NBT
designator C?  Capacitance: 680pF  (hidden comment: *)
Capacitor, Ceramic (MLCC), 680pF, ±10%, 50V, X7R, ±10%, SMD 0402; Manufacturer: VIIYONG; Manufacturer Part Number: V681K0402X7R500NBT
footprint CAP-0402 (0402 (1005M) Capacitor)
pins: 1, 2

## V682K0402X7R500NBT
designator C?  Capacitance: 6.8nF  (hidden comment: *)
Capacitor, Ceramic (MLCC), 6.8nF, ±10%, 50V, X7R, ±10%, SMD 0402; Manufacturer: VIIYONG; Manufacturer Part Number: V682K0402X7R500NBT
footprint CAP-0402 (0402 (1005M) Capacitor)
pins: 1, 2

## V683K0402X5R250NBT
designator C?  Capacitance: 68nF  (hidden comment: *)
Capacitor, Ceramic (MLCC), 68nF, ±10%, 25V, X5R, ±10%, SMD 0402; Manufacturer: VIIYONG; Manufacturer Part Number: V683K0402X5R250NBT
footprint CAP-0402 (0402 (1005M) Capacitor)
pins: 1, 2

## V750J0402C0G500NBT
designator C?  Capacitance: 75pF  (hidden comment: *)
Capacitor, Ceramic (MLCC), 75pF, ±5%, 50V, C0G, ±5%, SMD 0402; Manufacturer: VIIYONG; Manufacturer Part Number: V750J0402C0G500NBT
footprint CAP-0402 (0402 (1005M) Capacitor)
pins: 1, 2

## V822K0402X7R500NBT
designator C?  Capacitance: 8.2nF  (hidden comment: *)
Capacitor, Ceramic (MLCC), 8.2nF, ±10%, 50V, X7R, ±10%, SMD 0402; Manufacturer: VIIYONG; Manufacturer Part Number: V822K0402X7R500NBT
footprint CAP-0402 (0402 (1005M) Capacitor)
pins: 1, 2

## V823K0402X5R250NBT
designator C?  Capacitance: 82nF  (hidden comment: *)
Capacitor, Ceramic (MLCC), 82nF, ±10%, 25V, X5R, ±10%, SMD 0402; Manufacturer: VIIYONG; Manufacturer Part Number: V823K0402X5R250NBT
footprint CAP-0402 (0402 (1005M) Capacitor)
pins: 1, 2

## VJ0402G104KXQCW1BC
designator C?  Capacitance: 100nF  (hidden comment: *)
Capacitor, Ceramic (MLCC), 100nF, ±10%, 10V, X5R, ±10%, SMD 0402; Manufacturer: Vishay Intertech; Manufacturer Part Number: VJ0402G104KXQCW1BC
footprint CAP-0402 (0402 (1005M) Capacitor)
pins: 1, 2

## VR75C0402C0G500NBT
designator C?  Capacitance: 0.75pF  (hidden comment: *)
Capacitor, Ceramic (MLCC), 0.75pF, ±0.25pF, 50V, C0G, ±0.25pF, SMD 0402; Manufacturer: VIIYONG; Manufacturer Part Number: VR75C0402C0G500NBT
footprint CAP-0402 (0402 (1005M) Capacitor)
pins: 1, 2

## WBM155R71C104KA01D
designator C?  Capacitance: 100nF  (hidden comment: *)
Capacitor, Ceramic (MLCC), 100nF, ±10%, ±10%, SMD 0402; Manufacturer: Murata Electronics; Manufacturer Part Number: WBM155R71C104KA01D
footprint CAP-0402 (0402 (1005M) Capacitor)
pins: 1, 2

## ZRB15XR60J106ME12D
designator C?  Capacitance: 10uF  (hidden comment: *)
Capacitor, Ceramic (MLCC), 10uF, ±20%, ±20%, SMD 0402; Manufacturer: Murata Electronics; Manufacturer Part Number: ZRB15XR60J106ME12D
footprint CAP-0402 (0402 (1005M) Capacitor)
pins: 1, 2

## ZRB15XR61A106ME01D
designator C?  Capacitance: 10uF  (hidden comment: *)
Capacitor, Ceramic (MLCC), 10uF, ±20%, ±20%, SMD 0402; Manufacturer: Murata Electronics; Manufacturer Part Number: ZRB15XR61A106ME01D
footprint CAP-0402 (0402 (1005M) Capacitor)
pins: 1, 2

## ZRB15XR61A475KE01D
designator C?  Capacitance: 4.7uF  (hidden comment: *)
Capacitor, Ceramic (MLCC), 4.7uF, ±10%, 10V, X5R, ±10%, SMD 0402; Manufacturer: Murata Electronics; Manufacturer Part Number: ZRB15XR61A475KE01D
footprint CAP-0402 (0402 (1005M) Capacitor)
pins: 1, 2

## ZRB157R61C225KE11D
designator C?  Capacitance: 2.2uF  (hidden comment: *)
Capacitor, Ceramic (MLCC), 2.2uF, ±10%, ±10%, SMD 0402; Manufacturer: Murata Electronics; Manufacturer Part Number: ZRB157R61C225KE11D
footprint CAP-0402 (0402 (1005M) Capacitor)
pins: 1, 2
